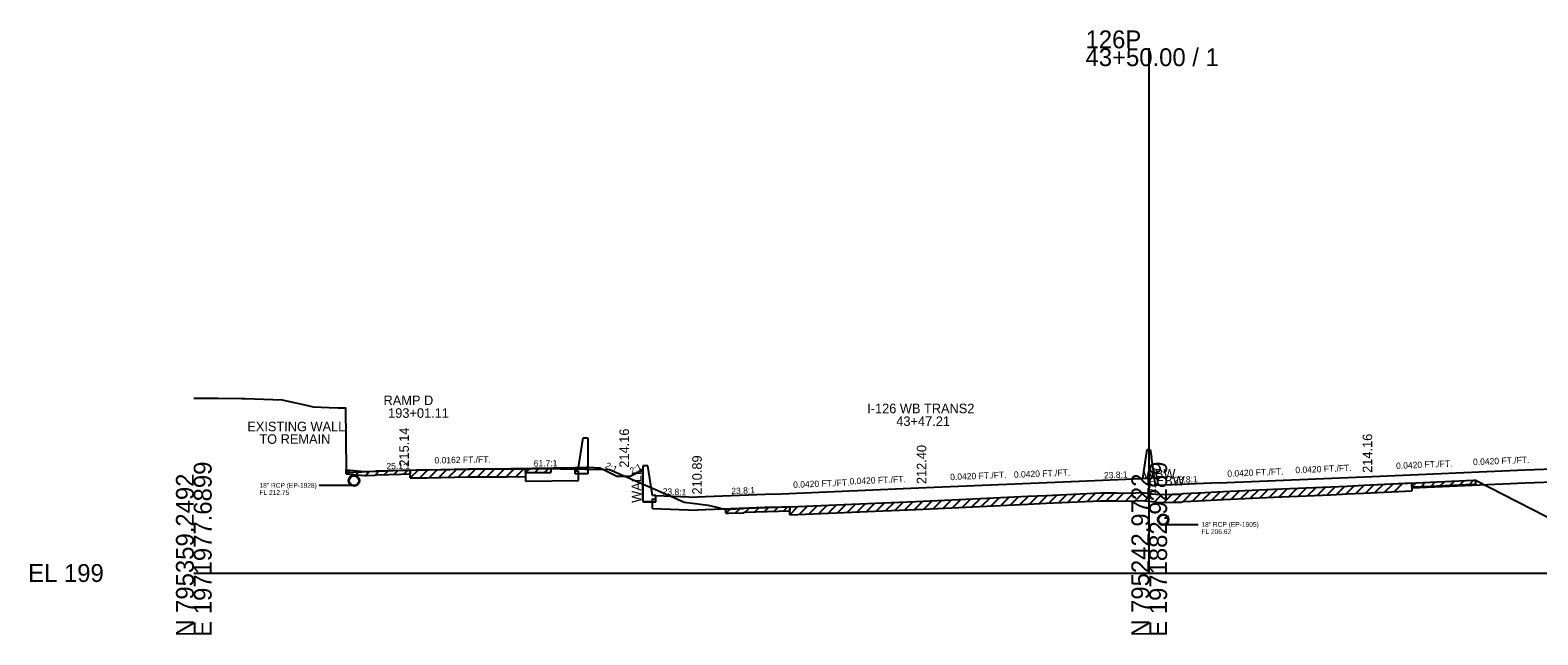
# Model space of a CAD drawing. Extents: x -161 to 1970889, y -4362 to 797231.
# Drawn here: x 974.3 to 1211, y 5990.3 to 6085.2 of the extents above; entities that cross this region are included whole.
import ezdxf

# ---------------------------------------------------------------- set-up
doc = ezdxf.new("R2010")
doc.units = 0
for name, color, linetype in [('RD_GPK_XS_Cell', 7, 'Continuous'), ('RD_XS_Base', 7, 'Continuous'), ('RD_XS_Box', 7, 'Continuous'), ('RD_XS_ExGround', 7, 'Continuous'), ('RD_XS_ExPaveRet', 7, 'Continuous'), ('RD_XS_MedBWall', 7, 'Continuous'), ('RD_XS_Misc_Line', 7, 'Continuous'), ('RD_XS_Pave', 7, 'Continuous'), ('RD_XS_PaveOvlay', 7, 'Continuous'), ('RD_XS_PaveShd', 7, 'Continuous'), ('RD_XS_Pipe', 7, 'Continuous'), ('RD_XS_TieSlope', 7, 'Continuous'), ('RD_XS_TX_Elev_EX', 7, 'Continuous'), ('RD_XS_TX_Elev_PR', 7, 'Continuous'), ('RD_XS_TX_Misc', 7, 'Continuous'), ('RD_XS_TX_MkPT', 7, 'Continuous'), ('RD_XS_TX_Notes', 7, 'Continuous'), ('RD_XS_TX_Profile', 7, 'Continuous'), ('RD_XS_TX_Slope', 7, 'Continuous'), ('RD_XS_TX_Station', 7, 'Continuous')]:
    doc.layers.add(name, color=color, linetype=linetype)

msp = doc.modelspace()

# ---------------------------------------------------------------- linework, layer by layer
at = {"layer": 'RD_GPK_XS_Cell'}
for p, q in [((1150, 6000), (1150, 6082.32)), ((1000, 6000), (1150, 6000)), ((1150, 6000), (1300, 6000))]:
    msp.add_line(p, q, dxfattribs=at)
at = {"layer": 'RD_XS_Base'}
for p, q in [((1059.87, 6015.99), (1059.87, 6016.55)), ((1060.38, 6016), (1059.87, 6015.99)), ((1060.38, 6014.52), (1060.38, 6016)), ((1209, 6014.13), (1230.81, 6015.04)), ((1052.05, 6014.39), (1060.38, 6014.52)), ((1191.23, 6013.38), (1209, 6014.13)), ((1072.01, 6010.14), (1072.01, 6011.62)), ((1072.01, 6011.62), (1072.51, 6011.6)), ((1072.01, 6010.14), (1079, 6009.85)), ((1072.51, 6011.6), (1072.51, 6012.16)), ((1091, 6010.35), (1079, 6009.85)), ((1091, 6010.35), (1093.55, 6010.46))]:
    msp.add_line(p, q, dxfattribs=at)
at = {"layer": 'RD_XS_Box'}
for p, q in [((1059.87, 6016.56), (1061.87, 6016.56)), ((1061.87, 6016.33), (1061.87, 6016.92)), ((1070.51, 6011.47), (1070.51, 6016.16)), ((1072.51, 6011.16), (1070.51, 6011.16))]:
    msp.add_line(p, q, dxfattribs=at)
at = {"layer": 'RD_XS_ExGround'}
msp.add_lwpolyline([(1000, 6027.44), (1003.8, 6027.41), (1007.5, 6027.38), (1008.06, 6027.36), (1013.88, 6027.16), (1014.55, 6026.99), (1017.44, 6026.37), (1018.74, 6026.08), (1021.24, 6025.98), (1022.6, 6025.91), (1023.81, 6025.92), (1023.93, 6016.2), (1026.78, 6015.91), (1027.09, 6015.92), (1028.42, 6015.96), (1028.7, 6016.05), (1032.48, 6016.13), (1034.95, 6016.18), (1036.56, 6016.21), (1043.14, 6016.33), (1049.19, 6016.36), (1052.31, 6016.37), (1052.86, 6016.37), (1056.07, 6016.4), (1057.58, 6016.37), (1065.26, 6016.23), (1074.9, 6012.04), (1077.01, 6011.14), (1078.71, 6010.89), (1080.74, 6010.67), (1081.4, 6010.49), (1081.92, 6010.36), (1083.54, 6009.99), (1083.94, 6010.01), (1086.23, 6010.1), (1086.45, 6010.16), (1094.83, 6010.42), (1106.97, 6010.95), (1113.37, 6011.24), (1119.02, 6011.5), (1124.5, 6011.76), (1130.94, 6012.06), (1133.8, 6012.19), (1142.33, 6012.59), (1143.26, 6012.6), (1144.88, 6012.6), (1145.15, 6012.52), (1147.84, 6012.58), (1148.89, 6012.61), (1149.7, 6012.54), (1150, 6012.5), (1151.61, 6012.32), (1153.58, 6012.35), (1155.01, 6012.39), (1155.29, 6012.49), (1156.55, 6012.55), (1157.71, 6012.59), (1161.64, 6012.78), (1169.49, 6013.16), (1178.49, 6013.54), (1181.09, 6013.65), (1183.62, 6013.77), (1193.01, 6014.22), (1200.89, 6014.56), (1201.23, 6014.58), (1227.58, 6001.07)], dxfattribs=at)
at = {"layer": 'RD_XS_ExPaveRet'}
for p, q in [((1023.93, 6015.57), (1023.93, 6016.2)), ((1023.93, 6015.57), (1026.78, 6015.28)), ((1026.78, 6015.28), (1027.09, 6015.29)), ((1027.09, 6015.29), (1028.42, 6015.34)), ((1028.42, 6015.34), (1028.7, 6015.43)), ((1028.7, 6015.43), (1032.48, 6015.51)), ((1032.48, 6015.51), (1033.97, 6015.54)), ((1033.97, 6014.91), (1033.97, 6016.16)), ((1033.97, 6016.16), (1033.97, 6015.54)), ((1033.97, 6014.91), (1034.95, 6014.93)), ((1034.95, 6014.93), (1036.56, 6014.96)), ((1036.56, 6014.96), (1043.14, 6015.08)), ((1043.14, 6015.08), (1049.19, 6015.11)), ((1049.19, 6015.11), (1052.05, 6015.12)), ((1052.05, 6016.37), (1052.05, 6015.12)), ((1052.05, 6015.75), (1052.05, 6016.37)), ((1052.05, 6015.75), (1052.31, 6015.75)), ((1052.31, 6015.75), (1052.86, 6015.75)), ((1052.86, 6015.75), (1056.07, 6015.78)), ((1056.07, 6016.4), (1056.07, 6015.78)), ((1201.23, 6014.58), (1201.23, 6013.95)), ((1169.49, 6011.91), (1178.49, 6012.29)), ((1178.49, 6012.29), (1181.09, 6012.4)), ((1181.09, 6012.4), (1183.62, 6012.52)), ((1183.62, 6012.52), (1191.23, 6012.88)), ((1191.23, 6014.13), (1191.23, 6012.88)), ((1191.23, 6013.51), (1191.23, 6014.13)), ((1191.23, 6013.51), (1193.01, 6013.59)), ((1193.01, 6013.59), (1200.89, 6013.94)), ((1200.89, 6013.94), (1201.23, 6013.95)), ((1083.54, 6009.37), (1083.54, 6009.99)), ((1093.55, 6009.13), (1093.55, 6010.38)), ((1093.55, 6010.38), (1093.55, 6009.75)), ((1106.97, 6009.7), (1113.37, 6009.99)), ((1113.37, 6009.99), (1119.02, 6010.25)), ((1119.02, 6010.25), (1124.5, 6010.51)), ((1124.5, 6010.51), (1130.94, 6010.81)), ((1130.94, 6010.81), (1133.8, 6010.94)), ((1133.8, 6010.94), (1142.33, 6011.34)), ((1142.33, 6011.34), (1143.26, 6011.35)), ((1143.26, 6011.35), (1144.88, 6011.35)), ((1144.88, 6011.35), (1145.15, 6011.27)), ((1145.15, 6011.27), (1147.84, 6011.33)), ((1147.84, 6011.33), (1148.89, 6011.36)), ((1148.89, 6011.36), (1149.7, 6011.29)), ((1149.7, 6011.29), (1150, 6011.25)), ((1150, 6011.25), (1151.61, 6011.07)), ((1151.61, 6011.07), (1153.58, 6011.1)), ((1153.58, 6011.1), (1155.01, 6011.14)), ((1155.01, 6011.14), (1155.29, 6011.24)), ((1155.29, 6011.24), (1156.55, 6011.3)), ((1156.55, 6011.3), (1157.71, 6011.34)), ((1157.71, 6011.34), (1161.64, 6011.53)), ((1161.64, 6011.53), (1169.49, 6011.91)), ((1083.54, 6009.37), (1083.94, 6009.39)), ((1083.94, 6009.39), (1086.23, 6009.47)), ((1086.23, 6009.47), (1086.45, 6009.54)), ((1086.45, 6009.54), (1093.55, 6009.75)), ((1093.55, 6009.13), (1094.83, 6009.17)), ((1094.83, 6009.17), (1106.97, 6009.7))]:
    msp.add_line(p, q, dxfattribs=at)
at = {"layer": 'RD_XS_MedBWall'}
for p, q in [((1060.37, 6016.56), (1061.12, 6021.23)), ((1061.12, 6021.23), (1061.87, 6021.23)), ((1061.87, 6021.23), (1061.87, 6015.56)), ((1149, 6014.83), (1149.67, 6019.37)), ((1149.67, 6019.37), (1150.16, 6019.37)), ((1150.16, 6019.37), (1150.33, 6018.19)), ((1151, 6013.73), (1150.33, 6018.19)), ((1059.87, 6015.56), (1059.87, 6016.56)), ((1059.87, 6016.56), (1060.37, 6016.56)), ((1061.87, 6015.56), (1059.87, 6015.56)), ((1071.26, 6016.82), (1070.51, 6016.82)), ((1070.51, 6016.82), (1070.51, 6011.16)), ((1072.01, 6012.16), (1071.26, 6016.82)), ((1070.51, 6011.16), (1072.51, 6011.16)), ((1072.51, 6012.16), (1072.01, 6012.16)), ((1072.51, 6011.16), (1072.51, 6012.16))]:
    msp.add_line(p, q, dxfattribs=at)
at = {"layer": 'RD_XS_Misc_Line'}
for p, q in [((1023.93, 6015.57), (1024.5, 6016.14)), ((1025.43, 6015.42), (1026, 6015.99)), ((1026.94, 6015.29), (1027.59, 6015.94)), ((1028.45, 6015.35), (1029.16, 6016.06)), ((1029.95, 6015.45), (1030.59, 6016.09)), ((1031.46, 6015.49), (1032.1, 6016.13)), ((1032.97, 6015.52), (1033.61, 6016.15)), ((1033.97, 6014.91), (1035.25, 6016.18)), ((1035.48, 6014.94), (1036.75, 6016.21)), ((1036.98, 6014.97), (1038.26, 6016.24)), ((1038.49, 6014.99), (1039.77, 6016.27)), ((1040, 6015.02), (1041.28, 6016.3)), ((1041.5, 6015.05), (1042.78, 6016.32)), ((1043.01, 6015.08), (1044.27, 6016.34)), ((1044.52, 6015.09), (1045.78, 6016.34)), ((1046.02, 6015.09), (1047.28, 6016.35)), ((1047.53, 6015.1), (1048.79, 6016.35)), ((1049.04, 6015.1), (1050.3, 6016.36)), ((1050.54, 6015.11), (1051.8, 6016.37)), ((1052.05, 6015.75), (1052.68, 6016.37)), ((1053.56, 6015.75), (1054.19, 6016.38)), ((1055.07, 6015.77), (1055.7, 6016.4)), ((1132.72, 6010.89), (1134.03, 6012.2)), ((1134.22, 6010.96), (1135.54, 6012.27)), ((1135.73, 6011.03), (1137.05, 6012.34)), ((1137.24, 6011.1), (1138.55, 6012.41)), ((1138.74, 6011.17), (1140.06, 6012.48)), ((1140.25, 6011.24), (1141.57, 6012.55)), ((1141.76, 6011.31), (1143.04, 6012.6)), ((1143.26, 6011.35), (1144.52, 6012.6)), ((1144.77, 6011.35), (1145.96, 6012.54)), ((1146.28, 6011.29), (1147.56, 6012.57)), ((1147.78, 6011.33), (1149.06, 6012.6)), ((1149.29, 6011.33), (1150.42, 6012.46)), ((1150.8, 6011.16), (1151.97, 6012.33)), ((1152.3, 6011.08), (1153.58, 6012.35)), ((1153.81, 6011.11), (1155.14, 6012.44)), ((1155.31, 6011.24), (1156.63, 6012.55)), ((1156.82, 6011.31), (1158.13, 6012.61)), ((1158.33, 6011.37), (1159.65, 6012.68)), ((1159.83, 6011.44), (1161.15, 6012.76)), ((1161.34, 6011.52), (1162.66, 6012.83)), ((1162.85, 6011.59), (1164.17, 6012.9)), ((1164.35, 6011.66), (1165.67, 6012.97)), ((1165.86, 6011.73), (1167.18, 6013.05)), ((1167.37, 6011.81), (1168.69, 6013.12)), ((1168.87, 6011.88), (1170.19, 6013.19)), ((1170.38, 6011.94), (1171.69, 6013.25)), ((1171.89, 6012.01), (1173.2, 6013.31)), ((1173.39, 6012.07), (1174.7, 6013.38)), ((1174.9, 6012.14), (1176.21, 6013.44)), ((1176.41, 6012.2), (1177.72, 6013.51)), ((1177.91, 6012.27), (1179.23, 6013.57)), ((1179.42, 6012.33), (1180.73, 6013.64)), ((1180.93, 6012.4), (1182.24, 6013.71)), ((1182.43, 6012.47), (1183.75, 6013.78)), ((1183.94, 6012.54), (1185.26, 6013.85)), ((1185.44, 6012.61), (1186.76, 6013.92)), ((1186.95, 6012.68), (1188.27, 6013.99)), ((1188.46, 6012.75), (1189.78, 6014.07)), ((1191.23, 6013.51), (1191.89, 6014.17)), ((1192.74, 6013.58), (1193.39, 6014.24)), ((1194.24, 6013.65), (1194.9, 6014.3)), ((1195.75, 6013.71), (1196.41, 6014.37)), ((1197.26, 6013.78), (1197.91, 6014.43)), ((1198.76, 6013.85), (1199.42, 6014.5)), ((1200.27, 6013.91), (1200.93, 6014.56)), ((1083.54, 6009.37), (1084.2, 6010.02)), ((1085.05, 6009.43), (1085.7, 6010.08)), ((1086.56, 6009.54), (1087.2, 6010.19)), ((1088.06, 6009.59), (1088.71, 6010.23)), ((1089.57, 6009.63), (1090.22, 6010.28)), ((1091.08, 6009.68), (1091.72, 6010.32)), ((1092.58, 6009.72), (1093.23, 6010.37)), ((1093.55, 6009.13), (1094.84, 6010.42)), ((1095.06, 6009.17), (1096.37, 6010.48)), ((1096.56, 6009.24), (1097.88, 6010.55)), ((1098.07, 6009.31), (1099.38, 6010.61)), ((1099.57, 6009.37), (1100.89, 6010.68)), ((1101.08, 6009.44), (1102.39, 6010.75)), ((1102.59, 6009.51), (1103.9, 6010.81)), ((1104.09, 6009.57), (1105.41, 6010.88)), ((1105.6, 6009.64), (1106.91, 6010.94)), ((1107.11, 6009.7), (1108.42, 6011.01)), ((1108.61, 6009.77), (1109.93, 6011.08)), ((1110.12, 6009.84), (1111.44, 6011.15)), ((1111.63, 6009.91), (1112.94, 6011.22)), ((1113.13, 6009.98), (1114.45, 6011.29)), ((1114.64, 6010.05), (1115.96, 6011.36)), ((1116.15, 6010.12), (1117.46, 6011.43)), ((1117.65, 6010.19), (1118.97, 6011.5)), ((1119.16, 6010.26), (1120.48, 6011.57)), ((1120.67, 6010.33), (1121.98, 6011.64)), ((1122.17, 6010.4), (1123.49, 6011.71)), ((1123.68, 6010.47), (1125, 6011.78)), ((1125.19, 6010.54), (1126.5, 6011.85)), ((1126.69, 6010.61), (1128.01, 6011.92)), ((1128.2, 6010.68), (1129.52, 6011.99)), ((1129.7, 6010.75), (1131.02, 6012.07)), ((1131.21, 6010.82), (1132.53, 6012.13))]:
    msp.add_line(p, q, dxfattribs=at)
at = {"layer": 'RD_XS_Pave'}
for p, q in [((1033.76, 6016.13), (1049.83, 6016.4)), ((1161, 6014.15), (1185, 6015.16)), ((1185, 6015.16), (1209, 6016.17)), ((1091, 6012.39), (1115, 6013.4)), ((1115, 6013.4), (1139, 6014.41))]:
    msp.add_line(p, q, dxfattribs=at)
at = {"layer": 'RD_XS_PaveOvlay'}
for p, q in [((1023.93, 6016.2), (1023.93, 6015.74)), ((1033.97, 6016.16), (1034.95, 6016.18)), ((1034.95, 6016.18), (1036.56, 6016.21)), ((1036.56, 6016.21), (1043.14, 6016.33)), ((1043.14, 6016.33), (1049.19, 6016.36)), ((1049.19, 6016.36), (1052.05, 6016.37)), ((1052.05, 6016.37), (1052.05, 6014.39)), ((1133.8, 6012.19), (1142.33, 6012.59)), ((1142.33, 6012.59), (1143.26, 6012.6)), ((1143.26, 6012.6), (1144.88, 6012.6)), ((1144.88, 6012.6), (1145.15, 6012.52)), ((1145.15, 6012.52), (1147.84, 6012.58)), ((1147.84, 6012.58), (1148.89, 6012.61)), ((1148.89, 6012.61), (1149.7, 6012.54)), ((1149.7, 6012.54), (1150, 6012.5)), ((1150, 6012.5), (1151.61, 6012.32)), ((1151.61, 6012.32), (1153.58, 6012.35)), ((1153.58, 6012.35), (1155.01, 6012.39)), ((1155.01, 6012.39), (1155.29, 6012.49)), ((1155.29, 6012.49), (1156.55, 6012.55)), ((1156.55, 6012.55), (1157.71, 6012.59)), ((1157.71, 6012.59), (1161.64, 6012.78)), ((1161.64, 6012.78), (1169.49, 6013.16)), ((1169.49, 6013.16), (1178.49, 6013.54)), ((1178.49, 6013.54), (1181.09, 6013.65)), ((1181.09, 6013.65), (1183.62, 6013.77)), ((1183.62, 6013.77), (1191.23, 6014.13)), ((1191.23, 6014.13), (1191.23, 6013.38)), ((1093.55, 6010.46), (1093.55, 6010.38)), ((1093.55, 6010.38), (1094.83, 6010.42)), ((1094.83, 6010.42), (1106.97, 6010.95)), ((1106.97, 6010.95), (1113.37, 6011.24)), ((1113.37, 6011.24), (1119.02, 6011.5)), ((1119.02, 6011.5), (1124.5, 6011.76)), ((1124.5, 6011.76), (1130.94, 6012.06)), ((1130.94, 6012.06), (1133.8, 6012.19))]:
    msp.add_line(p, q, dxfattribs=at)
msp.add_lwpolyline([(1023.93, 6016.2), (1026.78, 6015.91), (1027.09, 6015.92), (1028.42, 6015.96), (1028.7, 6016.05), (1032.48, 6016.13), (1033.97, 6016.16)], dxfattribs=at)
at = {"layer": 'RD_XS_PaveShd'}
for p, q in [((1209, 6016.17), (1230.81, 6017.08)), ((1033.76, 6016.13), (1023.93, 6015.74)), ((1049.83, 6016.4), (1059.87, 6016.56)), ((1139, 6014.41), (1150, 6014.87)), ((1150, 6013.69), (1150, 6014.87)), ((1091, 6012.39), (1079, 6011.89)), ((1161, 6014.15), (1150, 6013.69)), ((1072.51, 6012.16), (1079, 6011.89))]:
    msp.add_line(p, q, dxfattribs=at)
at = {"layer": 'RD_XS_Pipe'}
for p, q in [((1024.66, 6013.75), (1019.66, 6013.75)), ((1152.69, 6007.62), (1157.69, 6007.62))]:
    msp.add_line(p, q, dxfattribs=at)
for centre, radius in [((1025.16, 6014.5), 0.85), ((1025.16, 6014.5), 0.75), ((1152.19, 6008.37), 0.85), ((1152.19, 6008.37), 0.75)]:
    msp.add_circle(centre, radius, dxfattribs=at)
at = {"layer": 'RD_XS_TieSlope'}
for p, q in [((1063.87, 6016.47), (1061.87, 6016.55)), ((1063.87, 6016.47), (1064.51, 6016.16)), ((1064.51, 6016.16), (1066.51, 6015.16)), ((1068.51, 6015.16), (1066.51, 6015.16)), ((1070.51, 6016.16), (1068.51, 6015.16))]:
    msp.add_line(p, q, dxfattribs=at)

# ---------------------------------------------------------------- texts
at = {"layer": 'RD_GPK_XS_Cell'}
for s, p in [('126P', (1140, 6082.32)), ('43+50.00 / 1', (1140, 6079.52)), ('EL 199', (974, 5998.6))]:
    msp.add_text(s, height=2.8, dxfattribs=at).set_placement(p)
for s, p in [('E 1971977.6899', (1002.8, 5990)), ('E 1971882.9289', (1152.8, 5990)), ('N 795359.2492', (1000, 5990)), ('N 795242.9722', (1150, 5990))]:
    msp.add_text(s, height=2.8, rotation=90, dxfattribs=at).set_placement(p)
at = {"layer": 'RD_XS_Pipe'}
for s, p in [('18" RCP (EP-1928)', (1010.31, 6013.38)), ('FL 212.75', (1010.31, 6012.25)), ('18" RCP (EP-1905)', (1158.19, 6007.25)), ('FL 206.62', (1158.19, 6006.12))]:
    msp.add_text(s, height=0.75, dxfattribs=at).set_placement(p)
at = {"layer": 'RD_XS_TX_Elev_EX'}
msp.add_text('211.50', height=1, rotation=90, dxfattribs=at).set_placement((1151, 6012.5))
at = {"layer": 'RD_XS_TX_Elev_PR'}
for s, p in [(' 215.14', (1033.76, 6016.13)), (' 214.16', (1185, 6015.16)), (' 212.40', (1115, 6013.4))]:
    msp.add_text(s, height=1.5, rotation=90, dxfattribs=at).set_placement(p)
at = {"layer": 'RD_XS_TX_Misc'}
for s, p in [('214.16', (1068.32, 6016.53)), ('210.89', (1079.75, 6012.32))]:
    msp.add_text(s, height=1.5, rotation=90, dxfattribs=at).set_placement(p)
at = {"layer": 'RD_XS_TX_MkPT'}
for s, p in [('WBW', (1149, 6014.83)), ('EBW', (1151, 6013.73))]:
    msp.add_text(s, height=1.5, dxfattribs=at).set_placement(p)
at = {"layer": 'RD_XS_TX_Notes'}
for s, p in [('EXISTING WALL', (1008.4, 6022.24)), ('TO REMAIN', (1010.29, 6020.27))]:
    msp.add_text(s, height=1.5, dxfattribs=at).set_placement(p)
msp.add_text('WALL', height=1.5, rotation=90, dxfattribs=at).set_placement((1070.26, 6011.01))
at = {"layer": 'RD_XS_TX_Profile'}
for s, rotation, p in [('61.7:1', 0.9285, (1053.37, 6016.7)), ('23.8:1', 2.405, (1142.91, 6014.82)), ('23.8:1', 2.405, (1153.91, 6014.1)), ('23.8:1', 357.595, (1073.59, 6012.32)), ('23.8:1', 2.405, (1084.41, 6012.36))]:
    msp.add_text(s, height=1, rotation=rotation, dxfattribs=at).set_placement(p)
at = {"layer": 'RD_XS_TX_Slope'}
for s, rotation, p in [('25.1:1', 2.2804, (1030.26, 6016.24)), ('0.0162 FT./FT.', 0.9285, (1037.79, 6017.19)), ('2:1', 333.4883, (1064.5, 6016.55)), ('2:1', 26.5651, (1068.75, 6015.49)), ('0.0420 FT./FT.', 2.405, (1172.96, 6015.65)), ('0.0420 FT./FT.', 2.405, (1188.77, 6016.32)), ('0.0420 FT./FT.', 2.405, (1200.85, 6016.92)), ('0.0420 FT./FT.', 2.405, (1094.11, 6013.35)), ('0.0420 FT./FT.', 2.405, (1102.96, 6013.89)), ('0.0420 FT./FT.', 2.405, (1118.77, 6014.56)), ('0.0420 FT./FT.', 2.405, (1128.77, 6014.93)), ('0.0420 FT./FT.', 2.405, (1162.28, 6015.08))]:
    msp.add_text(s, height=1, rotation=rotation, dxfattribs=at).set_placement(p)
at = {"layer": 'RD_XS_TX_Station'}
for s, p in [('RAMP D', (1029.79, 6026.35)), ('I-126 WB TRANS2', (1105.72, 6025.07)), ('193+01.11', (1030.51, 6024.35)), ('43+47.21', (1110.29, 6023.07))]:
    msp.add_text(s, height=1.5, dxfattribs=at).set_placement(p)

doc.saveas('drawing.dxf')
